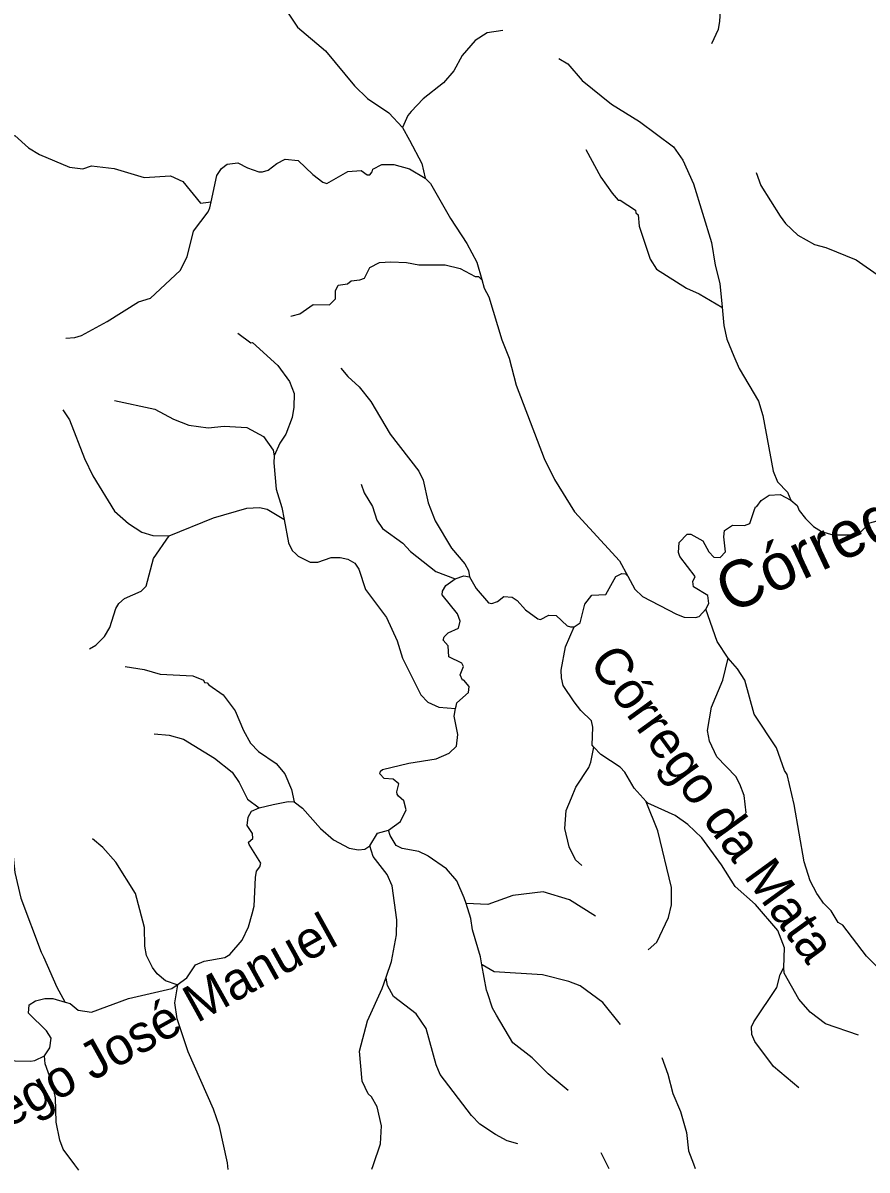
# Model space of a CAD drawing. Extents: x 393 to 446.6, y 8175.5 to 8231.
# Drawn here: x 440.612 to 444.228, y 8175.653 to 8180.565 of the extents above; entities that cross this region are included whole.
import ezdxf
from ezdxf.enums import TextEntityAlignment as Align

# ---------------------------------------------------------------- set-up
doc = ezdxf.new("R2010")
doc.units = 0
doc.header["$LTSCALE"] = 0.064
doc.layers.add('61', color=7, linetype='Continuous')
doc.layers.add('7', color=7, linetype='Continuous', lineweight=25)

msp = doc.modelspace()

# ---------------------------------------------------------------- linework, layer by layer
at = {"layer": '7'}
msp.add_line((443.0878, 8175.7286), (443.1219, 8175.659), dxfattribs=at)
for points in [[(443.5629, 8180.4772), (443.591, 8180.5383), (443.5975, 8180.5706), (443.6088, 8180.774), (443.604, 8180.8063), (443.6072, 8180.9032), (443.583, 8181.0033), (443.562, 8181.0582), (443.528, 8181.1237)], [(441.7373, 8180.6245), (441.7889, 8180.5463), (441.9084, 8180.4462), (442.0328, 8180.296), (442.0877, 8180.2412), (442.1797, 8180.1797), (442.2383, 8180.1178)], [(442.6676, 8180.533), (442.6012, 8180.5221), (442.5495, 8180.4898), (442.493, 8180.4252), (442.4575, 8180.3606), (442.4139, 8180.309), (442.3267, 8180.2395), (442.275, 8180.1862), (442.2604, 8180.1685), (442.2383, 8180.1178)], [(442.907, 8180.4127), (442.9454, 8180.3894), (443.0081, 8180.3187), (443.1325, 8180.2169), (443.2536, 8180.1426), (443.3989, 8180.0344), (443.4392, 8179.9779), (443.4845, 8179.8762), (443.562, 8179.6243), (443.5765, 8179.5274), (443.5975, 8179.4499), (443.6066, 8179.348)], [(440.5499, 8180.1167), (440.5721, 8180.0818), (440.5778, 8180.0829), (440.636, 8180.0296), (440.6828, 8180.0021), (440.812, 8179.9472), (440.8685, 8179.9408), (440.9057, 8179.9537), (441.0026, 8179.9424), (441.1317, 8179.9036), (441.2448, 8179.9101), (441.2965, 8179.8859), (441.3723, 8179.7938), (441.4184, 8179.7987)], [(442.2383, 8180.1178), (442.2674, 8180.063), (442.3202, 8179.9634), (442.3347, 8179.9007)], [(443.0235, 8180.0226), (443.0872, 8179.9053), (443.1357, 8179.8358), (443.1615, 8179.8067), (443.1696, 8179.8067), (443.2358, 8179.7631), (443.2374, 8179.7519), (443.2471, 8179.7438), (443.2519, 8179.6954), (443.2988, 8179.5533), (443.3262, 8179.5113), (443.4538, 8179.4289), (443.5087, 8179.4046), (443.6056, 8179.3486), (443.6066, 8179.348)], [(441.4184, 8179.7987), (441.4434, 8179.9117), (441.4628, 8179.9424), (441.487, 8179.9601), (441.5322, 8179.9666), (441.5742, 8179.944), (441.6226, 8179.9278), (441.6388, 8179.9278), (441.663, 8179.9343), (441.7002, 8179.9634), (441.7357, 8179.9811), (441.7906, 8179.9763), (441.8535, 8179.9165), (441.8972, 8179.8826), (441.9133, 8179.8778), (441.9439, 8179.8953), (442.0037, 8179.9295), (442.0602, 8179.9327), (442.0861, 8179.9149), (442.0974, 8179.9149), (442.1087, 8179.9279), (442.1103, 8179.9392), (442.1491, 8179.9585), (442.2007, 8179.9585), (442.2686, 8179.9408), (442.3347, 8179.9007)], [(443.7528, 8179.9252), (443.7726, 8179.8693), (443.8559, 8179.7373), (443.8785, 8179.7066), (443.9318, 8179.6566), (444.0028, 8179.6162), (444.0513, 8179.6033), (444.1805, 8179.55), (444.2854, 8179.4773), (444.3445, 8179.4479)], [(442.3347, 8179.9007), (442.358, 8179.8775), (442.4429, 8179.7276), (442.514, 8179.621), (442.556, 8179.5403), (442.5775, 8179.4658)], [(440.7966, 8179.2153), (440.8339, 8179.2177), (440.863, 8179.227), (440.9735, 8179.2868), (441.1075, 8179.3707), (441.1592, 8179.3869), (441.2851, 8179.5048), (441.3158, 8179.5629), (441.3432, 8179.6727), (441.4062, 8179.7567), (441.4127, 8179.7729), (441.4184, 8179.7987)], [(441.7601, 8179.3097), (441.7651, 8179.3109), (441.7986, 8179.3191), (441.8551, 8179.3594), (441.9246, 8179.3578), (441.9504, 8179.3837), (441.9504, 8179.4176), (441.9617, 8179.4418), (442.0021, 8179.4482), (442.0183, 8179.4612), (442.0554, 8179.4644), (442.0748, 8179.4725), (442.0974, 8179.5177), (442.1394, 8179.5387), (442.1878, 8179.5419), (442.2556, 8179.5387), (442.3073, 8179.529), (442.4204, 8179.529), (442.4849, 8179.5129), (442.5495, 8179.4789), (442.5641, 8179.479), (442.5752, 8179.4681), (442.5775, 8179.4658)], [(442.5775, 8179.4658), (442.588, 8179.4296), (442.6076, 8179.3918), (442.6641, 8179.2077), (442.6948, 8179.1302), (442.7255, 8179.0139), (442.845, 8178.7006), (442.8886, 8178.6102), (442.9742, 8178.4713), (443.168, 8178.2614), (443.2035, 8178.1962)], [(443.6066, 8179.348), (443.6136, 8179.269), (443.6266, 8179.2109), (443.6571, 8179.1388), (443.6798, 8179.085), (443.7622, 8178.9461), (443.7816, 8178.8847), (443.8252, 8178.6457), (443.8446, 8178.6005), (443.8872, 8178.5559), (443.9012, 8178.5216)], [(441.5332, 8179.2366), (441.5879, 8179.1959), (441.5952, 8179.1964), (441.7033, 8179.0979), (441.7534, 8179.0301), (441.7744, 8178.9784), (441.7728, 8178.9203), (441.7647, 8178.875), (441.7389, 8178.804), (441.713, 8178.7652), (441.6885, 8178.7111)], [(441.9735, 8179.0872), (442.0037, 8179.051), (442.0521, 8179.0074), (442.1022, 8178.9445), (442.1845, 8178.804), (442.3073, 8178.6457), (442.3267, 8178.607), (442.3476, 8178.5101), (442.3783, 8178.4326), (442.4478, 8178.3163), (442.5043, 8178.2485), (442.5207, 8178.22), (442.5246, 8178.1933)], [(441.0045, 8178.9489), (441.177, 8178.9105), (441.2577, 8178.8685), (441.3223, 8178.8427), (441.4063, 8178.8314), (441.4741, 8178.8379), (441.5709, 8178.833), (441.642, 8178.7943), (441.6838, 8178.7361), (441.6885, 8178.7111)], [(440.783, 8178.9081), (440.812, 8178.8653), (440.8766, 8178.7006), (440.9121, 8178.6264), (441.0042, 8178.4746), (441.0639, 8178.4212), (441.1221, 8178.3841), (441.1689, 8178.3696), (441.2391, 8178.3687)], [(441.6885, 8178.7111), (441.6873, 8178.6808), (441.6969, 8178.5682), (441.7211, 8178.4907), (441.731, 8178.4391)], [(442.0602, 8178.5893), (442.0742, 8178.5532), (442.1091, 8178.4944), (442.128, 8178.4358), (442.1523, 8178.4003), (442.2395, 8178.3373), (442.2718, 8178.3017), (442.38, 8178.2162), (442.4641, 8178.1852)], [(443.5374, 8178.0552), (443.5507, 8178.0789), (443.5458, 8178.1129), (443.4845, 8178.15), (443.4812, 8178.1726), (443.4909, 8178.1952), (443.4263, 8178.2808), (443.4199, 8178.2969), (443.4231, 8178.3405), (443.457, 8178.376), (443.4732, 8178.376), (443.5249, 8178.347), (443.5507, 8178.3002), (443.5717, 8178.2775), (443.5992, 8178.2759), (443.6217, 8178.3002), (443.6136, 8178.3648), (443.6169, 8178.3922), (443.6508, 8178.4148), (443.7025, 8178.4132), (443.7251, 8178.4213), (443.7444, 8178.4779), (443.7493, 8178.4923), (443.7558, 8178.4939), (443.7735, 8178.5198), (443.8091, 8178.5423), (443.8559, 8178.5456), (443.9012, 8178.5216)], [(441.2391, 8178.3687), (441.4289, 8178.4455), (441.571, 8178.4874), (441.6259, 8178.4907), (441.6582, 8178.4826), (441.7293, 8178.4401), (441.731, 8178.4391)], [(443.9012, 8178.5216), (443.928, 8178.4983), (443.9366, 8178.4778), (443.9641, 8178.4423), (443.998, 8178.4083), (444.0319, 8178.3873), (444.0804, 8178.3728), (444.1708, 8178.3728), (444.1966, 8178.3809), (444.2402, 8178.4245), (444.2709, 8178.4326), (444.3613, 8178.4099), (444.4776, 8178.3502), (444.5357, 8178.334), (444.5847, 8178.3451)], [(441.731, 8178.4391), (441.7502, 8178.3389), (441.7647, 8178.3066), (441.7804, 8178.2919), (441.7906, 8178.2824), (441.8423, 8178.2565), (441.8746, 8178.2565), (441.9327, 8178.2759), (441.9714, 8178.2759), (442.0037, 8178.2694), (442.0344, 8178.2517), (442.0505, 8178.2259), (442.0796, 8178.1387), (442.17, 8178.0192), (442.2152, 8177.9191), (442.2378, 8177.8448), (442.317, 8177.6881), (442.346, 8177.6558), (442.3929, 8177.6348), (442.4653, 8177.63), (442.4655, 8177.63)], [(440.898, 8177.8844), (440.9248, 8177.9007), (440.9622, 8177.9384), (440.9848, 8177.9756), (441.0106, 8178.058), (441.0235, 8178.0789), (441.0477, 8178.0999), (441.1188, 8178.1322), (441.1398, 8178.1532), (441.1721, 8178.2711), (441.2391, 8178.3687)], [(442.4641, 8178.1852), (442.5013, 8178.198), (442.5246, 8178.1933)], [(442.5246, 8178.1933), (442.5528, 8178.1435), (442.606, 8178.0821), (442.6206, 8178.0789), (442.6448, 8178.087), (442.6722, 8178.1096), (442.7078, 8178.1064), (442.7288, 8178.0918), (442.7643, 8178.0515), (442.8176, 8178.0127), (442.8289, 8178.0111), (442.8644, 8178.0288), (442.8967, 8178.0272), (442.9434, 8177.9831), (442.9573, 8177.9785), (442.9725, 8177.9796)], [(442.9725, 8177.9796), (442.9984, 8177.9966), (443.0194, 8178.0757), (443.0485, 8178.1144), (443.1083, 8178.1177), (443.1518, 8178.1952), (443.1767, 8178.2079), (443.193, 8178.2055), (443.2035, 8178.1962)], [(443.2035, 8178.1962), (443.2325, 8178.1403), (443.2665, 8178.1096), (443.4118, 8178.0337), (443.4441, 8178.0208), (443.4926, 8178.0192), (443.5087, 8178.024), (443.5374, 8178.0552)], [(442.4655, 8177.63), (442.4673, 8177.6397), (442.4708, 8177.6537), (442.5204, 8177.6978), (442.5237, 8177.7237), (442.5011, 8177.7511), (442.4946, 8177.7511), (442.4849, 8177.7737), (442.4994, 8177.8093), (442.4914, 8177.8238), (442.4365, 8177.8513), (442.4332, 8177.898), (442.4122, 8177.9223), (442.4171, 8177.9368), (442.4332, 8177.9529), (442.4785, 8177.974), (442.4849, 8178.003), (442.4736, 8178.0353), (442.4074, 8178.1161), (442.409, 8178.1322), (442.4236, 8178.1564), (442.4641, 8178.1852)], [(443.6322, 8177.8442), (443.5862, 8177.9158), (443.5374, 8178.0552)], [(443.0572, 8177.4644), (443.0499, 8177.472), (443.0534, 8177.5488), (443.0476, 8177.5767), (443.0016, 8177.6203), (442.9726, 8177.6575), (442.9257, 8177.7285), (442.9193, 8177.7608), (442.9177, 8177.7931), (442.9354, 8177.8932), (442.9725, 8177.9796)], [(441.0506, 8177.8095), (441.0775, 8177.8051), (441.1317, 8177.7963), (441.1996, 8177.7769), (441.34, 8177.7689), (441.3853, 8177.7511), (441.3901, 8177.7414), (441.4014, 8177.7398), (441.4078, 8177.7301), (441.4692, 8177.6881), (441.5209, 8177.6187), (441.5564, 8177.5348), (441.5871, 8177.4814), (441.621, 8177.4459), (441.6969, 8177.3942), (441.734, 8177.349), (441.7631, 8177.2829), (441.7742, 8177.2294)], [(443.7093, 8177.1825), (443.7008, 8177.257), (443.6831, 8177.3055), (443.6653, 8177.3378), (443.5846, 8177.4217), (443.5523, 8177.4895), (443.5442, 8177.5348), (443.562, 8177.6349), (443.6104, 8177.7511), (443.6322, 8177.8442)], [(444.2967, 8176.498), (444.2256, 8176.5691), (444.1239, 8176.7015), (444.1046, 8176.7128), (444.0739, 8176.7629), (444.0416, 8176.7952), (444.0198, 8176.8267), (444.0125, 8176.8372), (443.9834, 8176.8921), (443.9576, 8176.9728), (443.9156, 8177.2183), (443.8849, 8177.3474), (443.8736, 8177.3636), (443.8397, 8177.4605), (443.7444, 8177.6058), (443.7041, 8177.7511), (443.6734, 8177.7996), (443.6322, 8177.8442)], [(442.1784, 8177.1084), (442.2298, 8177.1456), (442.254, 8177.1957), (442.2443, 8177.2344), (442.2206, 8177.2534), (442.2156, 8177.2624), (442.2143, 8177.2724), (442.2217, 8177.3071), (442.1975, 8177.3264), (442.1588, 8177.3296), (442.1409, 8177.349), (442.1442, 8177.3604), (442.1523, 8177.3684), (442.2653, 8177.3959), (442.3816, 8177.4136), (442.4381, 8177.4378), (442.4688, 8177.4685), (442.4752, 8177.5186), (442.4591, 8177.5961), (442.4655, 8177.63)], [(441.1748, 8177.5209), (441.2383, 8177.5154), (441.2997, 8177.4976), (441.4321, 8177.4169), (441.508, 8177.3571), (441.5386, 8177.3119), (441.5742, 8177.2409), (441.624, 8177.2046)], [(443.0054, 8176.9568), (442.979, 8176.9809), (442.9516, 8177.0374), (442.9338, 8177.1149), (442.9387, 8177.1924), (442.9613, 8177.2463), (442.9806, 8177.2925), (443.0355, 8177.3765), (443.0452, 8177.3991), (443.0572, 8177.4644)], [(443.2813, 8177.2313), (443.2309, 8177.2877), (443.1906, 8177.3571), (443.1696, 8177.3781), (443.0872, 8177.433), (443.0572, 8177.4644)], [(440.5019, 8177.2781), (440.517, 8177.2517), (440.5698, 8176.9954), (440.5778, 8176.9276), (440.6037, 8176.8178), (440.6909, 8176.5853), (440.6997, 8176.5656), (440.7571, 8176.4367), (440.7917, 8176.3738), (440.7926, 8176.3722)], [(441.624, 8177.2046), (441.684, 8177.2182), (441.7486, 8177.2311), (441.7742, 8177.2294)], [(441.7742, 8177.2294), (441.8099, 8177.2021), (441.8874, 8177.1149), (441.9423, 8177.0664), (442.0102, 8177.0309), (442.0489, 8177.0244), (442.0764, 8177.0277), (442.0985, 8177.0411)], [(443.2901, 8176.5958), (443.3278, 8176.6288), (443.3779, 8176.7338), (443.3908, 8176.7887), (443.3908, 8176.863), (443.3311, 8177.1052), (443.2817, 8177.2304), (443.2813, 8177.2313)], [(443.8712, 8176.5197), (443.8747, 8176.6046), (443.8456, 8176.6791), (443.7493, 8176.7903), (443.6621, 8176.8678), (443.604, 8176.9599), (443.52, 8177.0762), (443.4602, 8177.1326), (443.4053, 8177.1714), (443.2885, 8177.2233), (443.2813, 8177.2313)], [(441.273, 8176.4466), (441.3142, 8176.4754), (441.3514, 8176.5319), (441.3885, 8176.5481), (441.4773, 8176.5626), (441.4983, 8176.5755), (441.5516, 8176.6369), (441.579, 8176.6951), (441.5944, 8176.7505), (441.6032, 8176.7823), (441.6081, 8176.905), (441.6129, 8176.9324), (441.6273, 8176.9509), (441.6307, 8176.9664), (441.5806, 8177.0471), (441.579, 8177.0568), (441.5968, 8177.0729), (441.5952, 8177.0939), (441.5725, 8177.1278), (441.5774, 8177.1634), (441.5919, 8177.1892), (441.624, 8177.2046)], [(441.273, 8176.4466), (441.2222, 8176.4625), (441.1866, 8176.4932), (441.1672, 8176.5207), (441.1414, 8176.5723), (441.1349, 8176.6111), (441.1333, 8176.6918), (441.1131, 8176.7676), (441.0946, 8176.8371), (441.0106, 8176.9712), (440.9541, 8177.0342), (440.9098, 8177.0715)], [(442.0985, 8177.0411), (442.1313, 8177.0955), (442.1784, 8177.1084)], [(442.5101, 8176.7937), (442.502, 8176.8193), (442.4704, 8176.8921), (442.4268, 8176.9421), (442.3481, 8176.9972), (442.3461, 8176.9986), (442.3073, 8177.0164), (442.2362, 8177.0293), (442.2113, 8177.0424), (442.1856, 8177.0854), (442.1784, 8177.1084)], [(442.1674, 8176.4784), (442.191, 8176.5465), (442.212, 8176.6595), (442.2136, 8176.7241), (442.1933, 8176.8701), (442.1724, 8176.9189), (442.113, 8176.9957), (442.0985, 8177.0411)], [(443.0639, 8176.7398), (442.9532, 8176.8097), (442.8402, 8176.8436), (442.711, 8176.829), (442.6028, 8176.7903), (442.5113, 8176.7937), (442.5101, 8176.7937)], [(442.5781, 8176.5314), (442.5717, 8176.5659), (442.5382, 8176.6821), (442.5301, 8176.7306), (442.5101, 8176.7937)], [(442.9479, 8175.993), (442.8612, 8176.0653), (442.7934, 8176.1331), (442.711, 8176.1977), (442.6399, 8176.3156), (442.6238, 8176.3463), (442.602, 8176.4115), (442.5979, 8176.4238), (442.5781, 8176.5314)], [(443.171, 8176.2755), (443.0953, 8176.3705), (442.9984, 8176.4415), (442.95, 8176.4609), (442.837, 8176.4883), (442.6303, 8176.5012), (442.5787, 8176.531), (442.5781, 8176.5314)], [(443.9352, 8176.0051), (443.8268, 8176.0959), (443.7477, 8176.2041), (443.7348, 8176.2332), (443.7331, 8176.2655), (443.7428, 8176.2881), (443.8413, 8176.435), (443.8559, 8176.49), (443.8712, 8176.5197)], [(444.191, 8176.2309), (444.0497, 8176.2784), (443.9834, 8176.3285), (443.935, 8176.385), (443.872, 8176.4964), (443.8712, 8176.5197)], [(442.106, 8175.6563), (442.1118, 8175.6729), (442.1442, 8175.7649), (442.1474, 8175.8425), (442.1296, 8175.9232), (442.1054, 8175.9668), (442.0909, 8175.9797), (442.0651, 8176.033), (442.0537, 8176.1622), (442.0877, 8176.2914), (442.1506, 8176.4302), (442.1674, 8176.4784)], [(442.7318, 8175.7647), (442.6864, 8175.7775), (442.6367, 8175.8053), (442.5689, 8175.8489), (442.5334, 8175.886), (442.3993, 8176.0621), (442.3816, 8176.1041), (442.3396, 8176.2591), (442.296, 8176.322), (442.1991, 8176.3963), (442.1733, 8176.4432), (442.1679, 8176.4752), (442.1674, 8176.4784)], [(440.7926, 8176.3722), (440.8143, 8176.3655), (440.8491, 8176.3382), (440.9056, 8176.3285), (441.0639, 8176.3882), (441.2496, 8176.4302), (441.273, 8176.4466)], [(441.4908, 8175.6546), (441.4877, 8175.6832), (441.4547, 8175.8392), (441.4288, 8175.9135), (441.3206, 8176.159), (441.2722, 8176.3011), (441.2625, 8176.3689), (441.2752, 8176.4459), (441.273, 8176.4466)], [(440.705, 8176.1419), (440.728, 8176.1767), (440.7328, 8176.2171), (440.7135, 8176.2494), (440.636, 8176.3252), (440.6392, 8176.3608), (440.6667, 8176.3769), (440.7054, 8176.3882), (440.741, 8176.3882), (440.7926, 8176.3722)], [(440.2419, 8175.8816), (440.2646, 8175.9232), (440.2694, 8175.991), (440.2872, 8176.0718), (440.3114, 8176.1105), (440.3324, 8176.1315), (440.3986, 8176.1508), (440.4438, 8176.1508), (440.5795, 8176.1202), (440.6441, 8176.1185), (440.6635, 8176.1218), (440.705, 8176.1419)], [(440.8521, 8175.6529), (440.835, 8175.6755), (440.7845, 8175.7423), (440.77, 8175.7811), (440.7539, 8175.8586), (440.7522, 8175.9619), (440.7409, 8176.0169), (440.707, 8176.1073), (440.705, 8176.1419)], [(443.3483, 8176.135), (443.3746, 8176.0637), (443.3957, 8175.9813), (443.428, 8175.9038), (443.4538, 8175.8134), (443.4635, 8175.7359), (443.4845, 8175.6793), (443.4917, 8175.6599)]]:
    msp.add_lwpolyline(points, dxfattribs=at)

# ---------------------------------------------------------------- texts
at = {"layer": '61'}
for s, height, rotation, p in [('Córrego José Manuel', 0.2, 25.191, (444.7981, 8178.5768)), ('Córrego da Mata', 0.16, 305.942, (443.5035, 8177.1768)), ('Córrego José Manuel', 0.16, 29.021, (441.0766, 8176.1249))]:
    msp.add_text(s, height=height, rotation=rotation, dxfattribs=at).set_placement(p, align=Align.CENTER)

doc.saveas('drawing.dxf')
